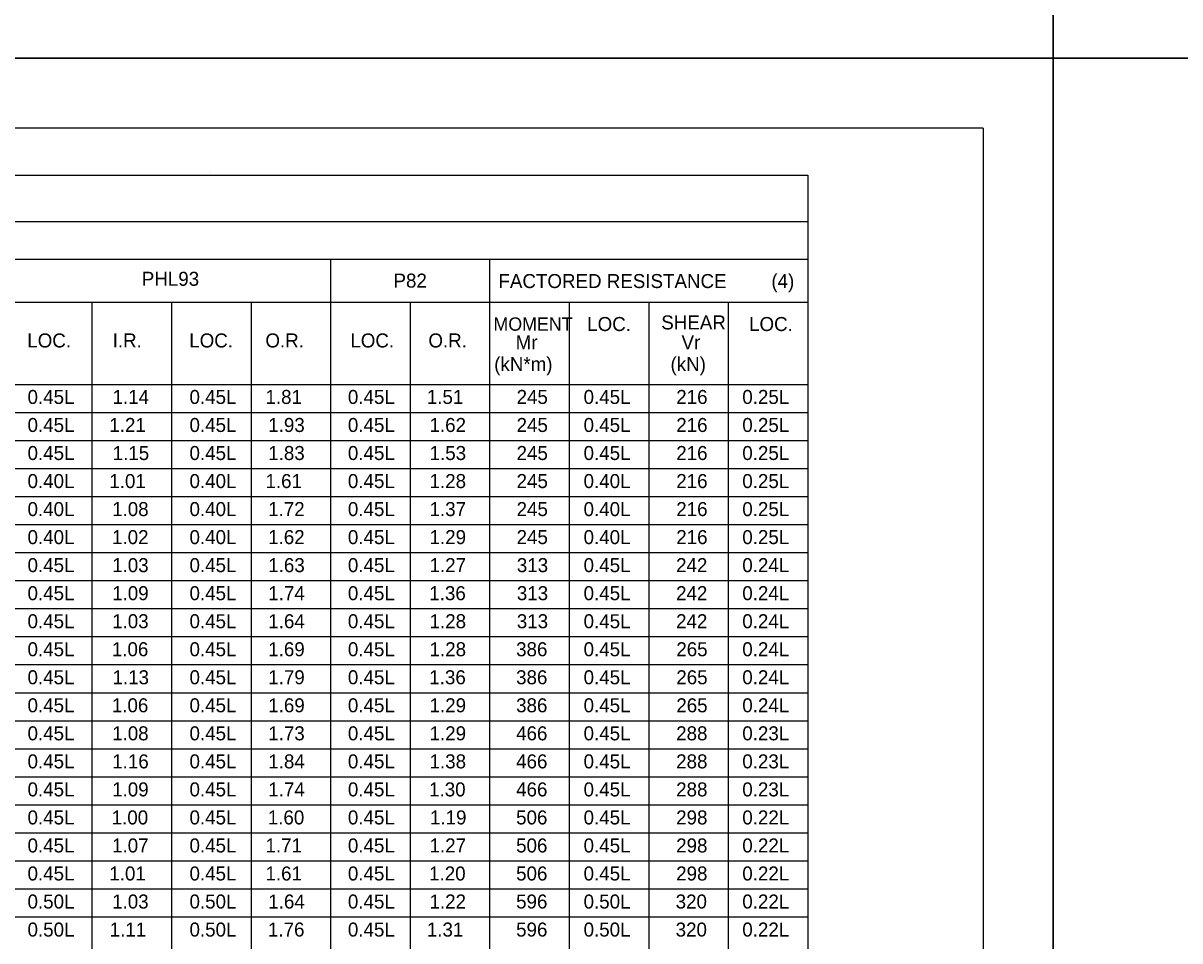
# Model space of a CAD drawing. Extents: x -5022 to -159, y 1126 to 7226.
# Drawn here: x -4060.5 to -3813, y 6282.9 to 6479.3 of the extents above; entities that cross this region are included whole.
import ezdxf

# ---------------------------------------------------------------- set-up
doc = ezdxf.new("R2010")
doc.units = 0
for name, color, linetype in [('2', 7, 'Continuous'), ('3', 7, 'Continuous'), ('PLT-BNDY', 7, 'Continuous')]:
    doc.layers.add(name, color=color, linetype=linetype)

msp = doc.modelspace()

# ---------------------------------------------------------------- linework, layer by layer
at = {"layer": '2'}
for q in [(-4641.13, 6456.81), (-3855.13, 5892.81)]:
    msp.add_line((-3855.13, 6456.81), q, dxfattribs=at)
at = {"layer": '3'}
for p, q in [((-4606.35, 6446.79), (-3892.63, 6446.79)), ((-4020.47, 6447.29), (-4020.47, 6447.29)), ((-3892.63, 6446.79), (-3892.63, 6095.98)), ((-4606.35, 6436.87), (-3892.63, 6436.87)), ((-4606.35, 6428.8), (-3892.63, 6428.8)), ((-3994.76, 6428.8), (-3994.76, 6095.98)), ((-3960.72, 6428.8), (-3960.72, 6095.98)), ((-4267.07, 6419.59), (-3892.63, 6419.59)), ((-4045.81, 6419.59), (-4045.81, 6095.98)), ((-4028.79, 6419.59), (-4028.79, 6095.98)), ((-4011.77, 6419.59), (-4011.77, 6095.98)), ((-3977.73, 6419.59), (-3977.73, 6095.98)), ((-3943.69, 6419.59), (-3943.69, 6095.98)), ((-3926.67, 6419.59), (-3926.67, 6095.98)), ((-3926.67, 6419.59), (-3926.67, 6095.98)), ((-3909.65, 6419.59), (-3909.65, 6095.98)), ((-4606.35, 6401.99), (-3892.63, 6401.99)), ((-4588.88, 6395.99), (-3892.63, 6395.99)), ((-4588.88, 6389.99), (-3892.63, 6389.99)), ((-4606.35, 6383.99), (-3892.63, 6383.99)), ((-4588.88, 6377.99), (-3892.63, 6377.99)), ((-4588.88, 6371.99), (-3892.63, 6371.99)), ((-4606.35, 6365.99), (-3892.63, 6365.99)), ((-4588.88, 6359.99), (-3892.63, 6359.99)), ((-4588.88, 6353.99), (-3892.63, 6353.99)), ((-4606.35, 6347.99), (-3892.63, 6347.99)), ((-4588.88, 6341.99), (-3892.63, 6341.99)), ((-4588.88, 6335.99), (-3892.63, 6335.99)), ((-4606.35, 6329.99), (-3892.63, 6329.99)), ((-4588.88, 6323.99), (-3892.63, 6323.99)), ((-4588.88, 6317.99), (-3892.63, 6317.99)), ((-4606.35, 6311.98), (-3892.63, 6311.99)), ((-4588.88, 6305.98), (-3892.63, 6305.99)), ((-4588.88, 6299.98), (-3892.63, 6299.99)), ((-4606.35, 6293.99), (-3892.63, 6293.99)), ((-4588.88, 6287.98), (-3892.63, 6287.99))]:
    msp.add_line(p, q, dxfattribs=at)
at = {"layer": 'PLT-BNDY'}
for points in [[(-4681.13, 7065.81), (-3840.13, 7065.81), (-3840.13, 6471.81), (-4681.13, 6471.81)], [(-3840.13, 7065.81), (-2999.13, 7065.81), (-2999.13, 6471.81), (-3840.13, 6471.81)], [(-4681.13, 6471.81), (-3840.13, 6471.81), (-3840.13, 5877.81), (-4681.13, 5877.81)], [(-3840.13, 6471.81), (-2999.13, 6471.81), (-2999.13, 5877.81), (-3840.13, 5877.81)]]:
    msp.add_lwpolyline(points, close=True, dxfattribs=at)

# ---------------------------------------------------------------- texts
at = {"layer": '2'}
for s, height, p in [('PHL93', 3, (-4035.15, 6423.08)), ('P82', 3, (-3981.29, 6422.69)), ('FACTORED RESISTANCE', 3.0001, (-3958.83, 6422.6)), ('(4)', 3, (-3900.43, 6422.6)), ('MOMENT', 2.85, (-3959.9, 6413.47)), ('LOC.', 3, (-3939.84, 6413.4)), ('SHEAR', 3, (-3923.99, 6413.74)), ('LOC.', 3, (-3905.2, 6413.4)), ('LOC.', 3, (-4059.66, 6409.88)), ('I.R.', 3, (-4041.38, 6409.88)), ('LOC.', 3, (-4025, 6409.88)), ('O.R.', 3, (-4008.7, 6409.88)), ('LOC.', 3, (-3990.52, 6409.88)), ('O.R.', 3, (-3973.82, 6409.88)), ('Mr', 3, (-3955.15, 6409.47)), ('Vr', 3, (-3919.65, 6409.47)), ('(kN*m)', 3, (-3959.74, 6404.82)), ('(kN)', 3, (-3922.01, 6404.82)), ('0.45L', 3, (-4059.6, 6397.79)), ('1.14', 3, (-4041.41, 6397.79)), ('0.45L', 3, (-4024.94, 6397.79)), ('1.81', 3, (-4008.69, 6397.79)), ('0.45L', 3, (-3991.05, 6397.79)), ('1.51', 3, (-3974.16, 6397.79)), ('245', 3, (-3954.95, 6397.79)), ('0.45L', 3, (-3940.61, 6397.79)), ('216', 3, (-3920.78, 6397.79)), ('0.25L', 3, (-3906.65, 6397.79)), ('0.45L', 3, (-4059.6, 6391.79)), ('1.21', 3, (-4042.1, 6391.79)), ('0.45L', 3, (-4024.94, 6391.79)), ('1.93', 3, (-4008.09, 6391.79)), ('0.45L', 3, (-3991.05, 6391.79)), ('1.62', 3, (-3973.58, 6391.79)), ('245', 3, (-3954.95, 6391.79)), ('0.45L', 3, (-3940.61, 6391.79)), ('216', 3, (-3920.78, 6391.79)), ('0.25L', 3, (-3906.65, 6391.79)), ('0.45L', 3, (-4059.6, 6385.79)), ('0.45L', 3, (-4024.94, 6385.79)), ('1.83', 3, (-4008.09, 6385.79)), ('0.45L', 3, (-3991.05, 6385.79)), ('1.53', 3, (-3973.56, 6385.79)), ('245', 3, (-3954.95, 6385.79)), ('0.45L', 3, (-3940.61, 6385.79)), ('216', 3, (-3920.78, 6385.79)), ('0.25L', 3, (-3906.65, 6385.79)), ('1.15', 3, (-4041.38, 6385.79)), ('0.40L', 3, (-4059.6, 6379.79)), ('1.01', 3, (-4042.1, 6379.79)), ('0.40L', 3, (-4024.94, 6379.79)), ('1.61', 3, (-4008.69, 6379.79)), ('0.45L', 3, (-3991.05, 6379.79)), ('1.28', 3, (-3973.57, 6379.79)), ('245', 3, (-3954.95, 6379.79)), ('0.40L', 3, (-3940.61, 6379.79)), ('216', 3, (-3920.78, 6379.79)), ('0.25L', 3, (-3906.65, 6379.79)), ('0.40L', 3, (-4059.6, 6373.79)), ('1.08', 3, (-4041.5, 6373.79)), ('0.40L', 3, (-4024.94, 6373.79)), ('1.72', 3, (-4008.11, 6373.79)), ('0.45L', 3, (-3991.05, 6373.79)), ('1.37', 3, (-3973.57, 6373.79)), ('245', 3, (-3954.95, 6373.79)), ('0.40L', 3, (-3940.61, 6373.79)), ('216', 3, (-3920.78, 6373.79)), ('0.25L', 3, (-3906.65, 6373.79)), ('0.40L', 3, (-4059.6, 6367.79)), ('1.02', 3, (-4041.52, 6367.79)), ('0.40L', 3, (-4024.94, 6367.79)), ('1.62', 3, (-4008.11, 6367.79)), ('0.45L', 3, (-3991.05, 6367.79)), ('1.29', 3, (-3973.57, 6367.79)), ('245', 3, (-3954.95, 6367.79)), ('0.40L', 3, (-3940.61, 6367.79)), ('216', 3, (-3920.78, 6367.79)), ('0.25L', 3, (-3906.65, 6367.79)), ('0.45L', 3, (-4059.6, 6361.79)), ('1.03', 3, (-4041.5, 6361.79)), ('0.45L', 3, (-4024.94, 6361.79)), ('1.63', 3, (-4008.09, 6361.79)), ('0.45L', 3, (-3991.05, 6361.79)), ('1.27', 3, (-3973.57, 6361.79)), ('313', 3, (-3954.9, 6361.79)), ('0.45L', 3, (-3940.61, 6361.79)), ('242', 3, (-3920.82, 6361.79)), ('0.24L', 3, (-3906.65, 6361.79)), ('0.45L', 3, (-4059.6, 6355.79)), ('1.09', 3, (-4041.5, 6355.79)), ('0.45L', 3, (-4024.94, 6355.79)), ('1.74', 3, (-4008.08, 6355.79)), ('0.45L', 3, (-3991.05, 6355.79)), ('1.36', 3, (-3973.63, 6355.79)), ('313', 3, (-3954.9, 6355.79)), ('0.45L', 3, (-3940.61, 6355.79)), ('242', 3, (-3920.82, 6355.79)), ('0.24L', 3, (-3906.65, 6355.79)), ('0.45L', 3, (-4059.6, 6349.79)), ('1.03', 3, (-4041.5, 6349.79)), ('0.45L', 3, (-4024.94, 6349.79)), ('1.64', 3, (-4008.08, 6349.79)), ('0.45L', 3, (-3991.05, 6349.79)), ('1.28', 3, (-3973.57, 6349.79)), ('313', 3, (-3954.9, 6349.79)), ('0.45L', 3, (-3940.61, 6349.79)), ('242', 3, (-3920.82, 6349.79)), ('0.24L', 3, (-3906.65, 6349.79)), ('0.45L', 3, (-4059.6, 6343.79)), ('1.06', 3, (-4041.56, 6343.79)), ('0.45L', 3, (-4024.94, 6343.79)), ('1.69', 3, (-4008.09, 6343.79)), ('0.45L', 3, (-3991.05, 6343.79)), ('1.28', 3, (-3973.57, 6343.79)), ('386', 3, (-3955.05, 6343.79)), ('0.45L', 3, (-3940.61, 6343.79)), ('265', 3, (-3920.77, 6343.79)), ('0.24L', 3, (-3906.65, 6343.79)), ('0.45L', 3, (-4059.6, 6337.79)), ('1.13', 3, (-4041.42, 6337.79)), ('0.45L', 3, (-4024.94, 6337.79)), ('1.79', 3, (-4008.09, 6337.79)), ('0.45L', 3, (-3991.05, 6337.79)), ('1.36', 3, (-3973.63, 6337.79)), ('386', 3, (-3955.05, 6337.79)), ('0.45L', 3, (-3940.61, 6337.79)), ('265', 3, (-3920.77, 6337.79)), ('0.24L', 3, (-3906.65, 6337.79)), ('0.45L', 3, (-4059.6, 6331.79)), ('1.06', 3, (-4041.56, 6331.79)), ('0.45L', 3, (-4024.94, 6331.79)), ('1.69', 3, (-4008.09, 6331.79)), ('0.45L', 3, (-3991.05, 6331.79)), ('1.29', 3, (-3973.57, 6331.79)), ('386', 3, (-3955.05, 6331.79)), ('0.45L', 3, (-3940.61, 6331.79)), ('265', 3, (-3920.77, 6331.79)), ('0.24L', 3, (-3906.65, 6331.79)), ('0.45L', 3, (-4059.6, 6325.79)), ('1.08', 3, (-4041.5, 6325.79)), ('0.45L', 3, (-4024.94, 6325.79)), ('1.73', 3, (-4008.09, 6325.79)), ('0.45L', 3, (-3991.05, 6325.79)), ('1.29', 3, (-3973.57, 6325.79)), ('466', 3, (-3955.05, 6325.79)), ('0.45L', 3, (-3940.61, 6325.79)), ('288', 3, (-3920.8, 6325.79)), ('0.23L', 3, (-3906.65, 6325.79)), ('0.45L', 3, (-4059.6, 6319.79)), ('1.16', 3, (-4041.48, 6319.79)), ('0.45L', 3, (-4024.94, 6319.79)), ('1.84', 3, (-4008.08, 6319.79)), ('0.45L', 3, (-3991.05, 6319.79)), ('1.38', 3, (-3973.57, 6319.79)), ('466', 3, (-3955.05, 6319.79)), ('0.45L', 3, (-3940.61, 6319.79)), ('288', 3, (-3920.8, 6319.79)), ('0.23L', 3, (-3906.65, 6319.79)), ('0.45L', 3, (-4059.6, 6313.79)), ('1.09', 3, (-4041.5, 6313.79)), ('0.45L', 3, (-4024.94, 6313.79)), ('1.74', 3, (-4008.08, 6313.79)), ('0.45L', 3, (-3991.05, 6313.79)), ('1.30', 3, (-3973.67, 6313.79)), ('466', 3, (-3955.05, 6313.79)), ('0.45L', 3, (-3940.61, 6313.79)), ('288', 3, (-3920.8, 6313.79)), ('0.23L', 3, (-3906.65, 6313.79)), ('0.45L', 3, (-4059.6, 6307.79)), ('1.00', 3, (-4041.6, 6307.79)), ('0.45L', 3, (-4024.94, 6307.79)), ('1.60', 3, (-4008.19, 6307.79)), ('0.45L', 3, (-3991.05, 6307.79)), ('1.19', 3, (-3973.48, 6307.79)), ('506', 3, (-3955.05, 6307.79)), ('0.45L', 3, (-3940.61, 6307.79)), ('298', 3, (-3920.8, 6307.79)), ('0.22L', 3, (-3906.65, 6307.79)), ('0.45L', 3, (-4059.6, 6301.79)), ('1.07', 3, (-4041.51, 6301.79)), ('0.45L', 3, (-4024.94, 6301.79)), ('1.71', 3, (-4008.69, 6301.79)), ('0.45L', 3, (-3991.05, 6301.79)), ('1.27', 3, (-3973.57, 6301.79)), ('506', 3, (-3955.05, 6301.79)), ('0.45L', 3, (-3940.61, 6301.79)), ('298', 3, (-3920.8, 6301.79)), ('0.22L', 3, (-3906.65, 6301.79)), ('0.45L', 3, (-4059.6, 6295.79)), ('1.01', 3, (-4042.1, 6295.79)), ('0.45L', 3, (-4024.94, 6295.79)), ('1.61', 3, (-4008.69, 6295.79)), ('0.45L', 3, (-3991.05, 6295.79)), ('1.20', 3, (-3973.67, 6295.79)), ('506', 3, (-3955.05, 6295.79)), ('0.45L', 3, (-3940.61, 6295.79)), ('298', 3, (-3920.8, 6295.79)), ('0.22L', 3, (-3906.65, 6295.79)), ('0.50L', 3, (-4059.6, 6289.79)), ('1.03', 3, (-4041.5, 6289.79)), ('0.50L', 3, (-4024.94, 6289.79)), ('1.64', 3, (-4008.08, 6289.79)), ('0.45L', 3, (-3991.05, 6289.79)), ('1.22', 3, (-3973.58, 6289.79)), ('596', 3, (-3955.05, 6289.79)), ('0.50L', 3, (-3940.61, 6289.79)), ('320', 3, (-3920.91, 6289.79)), ('0.22L', 3, (-3906.65, 6289.79)), ('0.50L', 3, (-4059.6, 6283.79)), ('1.11', 3, (-4042.02, 6283.79)), ('0.50L', 3, (-4024.94, 6283.79)), ('1.76', 3, (-4008.15, 6283.79)), ('0.45L', 3, (-3991.05, 6283.79)), ('1.31', 3, (-3974.16, 6283.79)), ('596', 3, (-3955.05, 6283.79)), ('0.50L', 3, (-3940.61, 6283.79)), ('320', 3, (-3920.91, 6283.79)), ('0.22L', 3, (-3906.65, 6283.79))]:
    msp.add_text(s, height=height, dxfattribs=at).set_placement(p)

doc.saveas('drawing.dxf')
